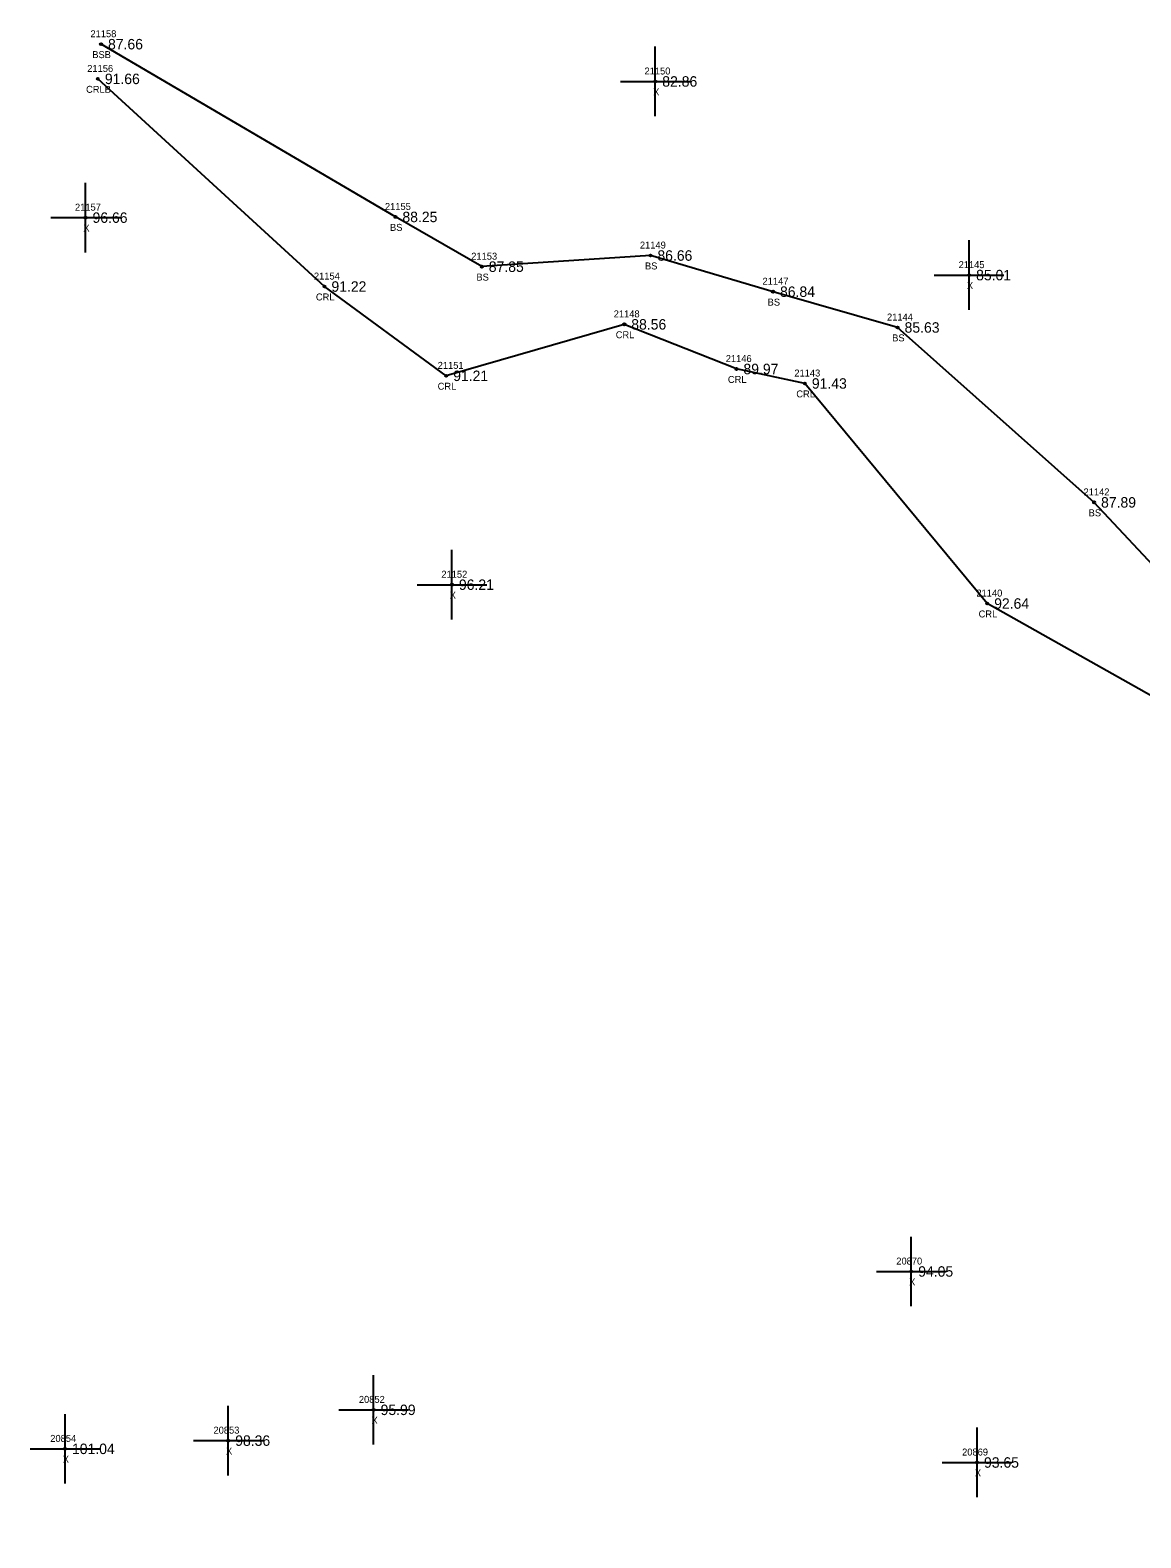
# Model space of a CAD drawing. Extents: x 2530197 to 2532051, y 935230 to 936631.
# Drawn here: x 2530785.2 to 2530944.6, y 935952.3 to 936168.7 of the extents above; entities that cross this region are included whole.
import ezdxf

# ---------------------------------------------------------------- set-up
doc = ezdxf.new("R2010")
doc.units = 0
for name, color, linetype in [('RD_DTM_BkLn2', 7, 'Continuous'), ('RD_DTM_BkLn_txCode', 7, 'Continuous'), ('RD_EX_H2O', 7, 'Continuous'), ('RD_EX_H2O_txCode', 7, 'Continuous'), ('RD_EX_Misc', 7, 'Continuous'), ('RD_EX_Misc_txCode', 7, 'Continuous'), ('RD_EX_TX_H2O_ELEV', 7, 'Continuous'), ('RD_EX_TX_Misc_ELEV', 7, 'Continuous'), ('RD_SMD_Locator', 7, 'Continuous')]:
    doc.layers.add(name, color=color, linetype=linetype)

msp = doc.modelspace()

# ---------------------------------------------------------------- linework, layer by layer
at = {"layer": 'RD_DTM_BkLn2'}
msp.add_lwpolyline([(2531052.84, 936091.07), (2531024.22, 936076.99), (2530987.08, 936088.8), (2530959.02, 936078.33), (2530937.87, 936100.94), (2530909.67, 936126.05), (2530891.79, 936131.19), (2530874.19, 936136.38), (2530849.99, 936134.78), (2530837.59, 936141.92), (2530795.33, 936166.72)], dxfattribs=at)
at = {"layer": 'RD_EX_H2O'}
msp.add_lwpolyline([(2531078.88, 935952.28), (2531078.88, 935952.28), (2531082.9, 935955.37), (2531071.89, 935962.43), (2531052.52, 935981.82), (2531042.66, 936018.54), (2531050.4, 936038.59), (2531079.35, 936050.48), (2531076.46, 936052.29), (2531062.77, 936059.41), (2531060.27, 936060.12), (2531061.98, 936077.76), (2531053.99, 936081.48), (2531023.23, 936060.57), (2531009.04, 936063.64), (2530981.92, 936072.85), (2530952.28, 936069.69), (2530922.53, 936086.42), (2530896.36, 936118.01), (2530886.54, 936120.09), (2530870.44, 936126.5), (2530844.88, 936119.11), (2530827.4, 936131.93), (2530794.88, 936161.74)], dxfattribs=at)
at = {"layer": 'RD_EX_Misc'}
for p, q in [((2530874.89, 936156.37), (2530874.89, 936166.37)), ((2530869.89, 936161.37), (2530879.89, 936161.37)), ((2530793.11, 936136.82), (2530793.11, 936146.82)), ((2530788.11, 936141.82), (2530798.11, 936141.82)), ((2530919.94, 936128.57), (2530919.94, 936138.57)), ((2530914.94, 936133.57), (2530924.94, 936133.57)), ((2530845.7, 936084.12), (2530845.7, 936094.12)), ((2530840.7, 936089.12), (2530850.7, 936089.12)), ((2530911.63, 935985.52), (2530911.63, 935995.52)), ((2530906.63, 935990.52), (2530916.63, 935990.52)), ((2530834.46, 935965.66), (2530834.46, 935975.66)), ((2530790.16, 935960.06), (2530790.16, 935970.06)), ((2530813.59, 935961.24), (2530813.59, 935971.24)), ((2530829.46, 935970.66), (2530839.46, 935970.66)), ((2530921.07, 935958.1), (2530921.07, 935968.1)), ((2530808.59, 935966.24), (2530818.59, 935966.24)), ((2530785.16, 935965.06), (2530795.16, 935965.06)), ((2530916.07, 935963.1), (2530926.07, 935963.1))]:
    msp.add_line(p, q, dxfattribs=at)
at = {"layer": 'RD_SMD_Locator'}
for centre in [(2530795.33, 936166.72), (2530794.88, 936161.74), (2530874.89, 936161.37), (2530793.11, 936141.82), (2530837.59, 936141.92), (2530874.19, 936136.38), (2530849.99, 936134.78), (2530827.4, 936131.93), (2530919.94, 936133.57), (2530891.79, 936131.19), (2530870.44, 936126.5), (2530909.67, 936126.05), (2530844.88, 936119.11), (2530886.54, 936120.09), (2530896.36, 936118.01), (2530937.87, 936100.94), (2530845.7, 936089.12), (2530922.53, 936086.42), (2530911.63, 935990.52), (2530834.46, 935970.66), (2530813.59, 935966.24), (2530790.16, 935965.06), (2530921.07, 935963.1)]:
    msp.add_circle(centre, 0.15, dxfattribs=at)

# ---------------------------------------------------------------- texts
at = {"layer": 'RD_DTM_BkLn_txCode'}
for s, p in [('21158', (2530793.81, 936167.72)), ('BSB', (2530794.07, 936164.72)), ('21155', (2530836.08, 936142.92)), ('BS', (2530836.81, 936139.92)), ('21153', (2530848.47, 936135.78)), ('21149', (2530872.68, 936137.38)), ('BS', (2530873.41, 936134.38)), ('BS', (2530849.21, 936132.78)), ('21147', (2530890.28, 936132.19)), ('BS', (2530891.01, 936129.19)), ('21144', (2530908.15, 936127.05)), ('BS', (2530908.89, 936124.05)), ('21142', (2530936.36, 936101.94)), ('BS', (2530937.09, 936098.94))]:
    msp.add_text(s, height=1, dxfattribs=at).set_placement(p)
at = {"layer": 'RD_EX_H2O_txCode'}
for s, p in [('21156', (2530793.35, 936162.74)), ('CRLB', (2530793.18, 936159.74)), ('21154', (2530825.89, 936132.93)), ('CRL', (2530826.17, 936129.93)), ('21148', (2530868.92, 936127.5)), ('CRL', (2530869.21, 936124.5)), ('21146', (2530885, 936121.09)), ('21151', (2530843.65, 936120.11)), ('CRL', (2530885.31, 936118.09)), ('21143', (2530894.85, 936119.01)), ('CRL', (2530843.65, 936117.11)), ('CRL', (2530895.13, 936116.01)), ('21140', (2530920.98, 936087.42)), ('CRL', (2530921.3, 936084.42))]:
    msp.add_text(s, height=1, dxfattribs=at).set_placement(p)
at = {"layer": 'RD_EX_Misc_txCode'}
for s, p in [('21150', (2530873.34, 936162.37)), ('X', (2530874.58, 936159.37)), ('21157', (2530791.59, 936142.82)), ('X', (2530792.79, 936139.82)), ('21145', (2530918.43, 936134.57)), ('X', (2530919.62, 936131.57)), ('21152', (2530844.18, 936090.12)), ('X', (2530845.38, 936087.12)), ('20870', (2530909.48, 935991.52)), ('X', (2530911.32, 935988.52)), ('20852', (2530832.34, 935971.66)), ('X', (2530834.15, 935968.66)), ('20853', (2530811.47, 935967.24)), ('20854', (2530788.04, 935966.06)), ('X', (2530789.84, 935963.06)), ('X', (2530813.27, 935964.24)), ('20869', (2530918.93, 935964.1)), ('X', (2530920.76, 935961.1))]:
    msp.add_text(s, height=1, dxfattribs=at).set_placement(p)
at = {"layer": 'RD_EX_TX_H2O_ELEV'}
for s, p in [('91.66', (2530795.88, 936160.99)), ('91.22', (2530828.4, 936131.18)), ('88.56', (2530871.44, 936125.75)), ('91.21', (2530845.88, 936118.36)), ('89.97', (2530887.54, 936119.34)), ('91.43', (2530897.36, 936117.26)), ('92.64', (2530923.53, 936085.67))]:
    msp.add_text(s, height=1.5, dxfattribs=at).set_placement(p)
at = {"layer": 'RD_EX_TX_Misc_ELEV'}
for s, p in [('87.66', (2530796.33, 936165.97)), ('82.86', (2530875.89, 936160.62)), ('96.66', (2530794.11, 936141.07)), ('88.25', (2530838.59, 936141.17)), ('86.66', (2530875.19, 936135.63)), ('87.85', (2530850.99, 936134.03)), ('85.01', (2530920.94, 936132.82)), ('86.84', (2530892.79, 936130.44)), ('85.63', (2530910.67, 936125.3)), ('87.89', (2530938.87, 936100.19)), ('96.21', (2530846.7, 936088.37)), ('94.05', (2530912.63, 935989.77)), ('95.99', (2530835.46, 935969.91)), ('101.04', (2530791.16, 935964.31)), ('98.36', (2530814.59, 935965.49)), ('93.65', (2530922.07, 935962.35))]:
    msp.add_text(s, height=1.5, dxfattribs=at).set_placement(p)

doc.saveas('drawing.dxf')
